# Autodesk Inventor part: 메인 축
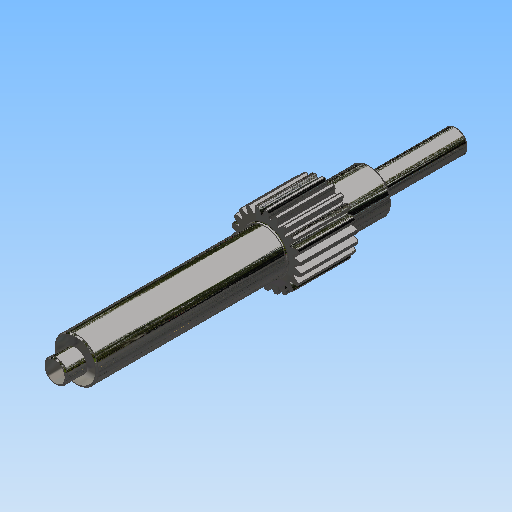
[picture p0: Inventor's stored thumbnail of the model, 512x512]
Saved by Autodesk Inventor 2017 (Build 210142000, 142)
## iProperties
Created: 2016-02
Part Number: 메인 축
Material: 강철, 연강
Document SubType Name: Modeling
Categories: <?xml version="1.0" encoding="UTF-16"?> <MemberInstance><Categories><FamilyTemplate><FamilyTemplateParameter ValueType="xs:double" Id="1" ObjectReferenceKey="da
Density: 7.86 g/cm^3
Mass: 187.503 g
Surface Area: 82.0529 cm^2
Volume: 23.8554 cm^3
Appearance: 강철 - 광택
Author: mdu
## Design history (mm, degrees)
sketch "Sketch1"
  geometry: C1 r 12 at (0, 0)
  constraints: 1 centre point
  dimensions: "d0" = 24 diameter of C1 (= da_da)
extrude "Extrusion1" new body sketch "Sketch1" distance "d1" = 20 (= da_b); taper "d2" = 0 deg
workplane "Work Plane2"
feature "피치 지름" dims "d4" = 10, "d5" = 0
workplane "Work Plane8"
workplane "Work Plane9"
chamfer "모따기1" distance "d49" = 0.2; stored, may be unused: second distance "d50" = 2, angle "d51" = 45 deg
sketch "스케치3"
  geometry: C1 r 7.5 at (0, 0); 1 further point
  constraints: 1 centre point, 1 coincident
  dimensions: "d52" = 15 diameter of C1
extrude "돌출2" join sketch "스케치3" distance "d53" = 66; taper "d54" = 0 deg
sketch "스케치4"
  geometry: C1 r 4 at (0, 0); 1 further point
  constraints: 1 centre point, 1 coincident
  dimensions: "d55" = 8 diameter of C1
extrude "돌출3" join sketch "스케치4" distance "d56" = 7; taper "d57" = 0 deg
sketch "스케치5"
  geometry: C1 r 7.5 at (0, 0) reference; C2 r 7.5 at (0, 0) reference; 1 further point
extrude "돌출4" join sketch "스케치5" distance "d62" = 16; taper "d63" = 0 deg
sketch "스케치6"
  geometry: C1 r 4 at (0, 0); 1 further point
  constraints: 1 centre point, 1 coincident
  dimensions: "d64" = 8 diameter of C1
extrude "돌출5" join sketch "스케치6" distance "d65" = 30; taper "d66" = 0 deg
chamfer "모따기2" distance "d58" = 0.5; stored, may be unused: second distance "d59" = 2, angle "d60" = 45 deg
fillet "모깎기1" dims "d61" = 0.5
feature "스퍼 기어" dims "da_b" = 20, "da_d" = 22, "da_aw" = 31, "da_da" = 24, "da_df" = 19.5, "da_dw" = 22, angle "da_beta" = 0 deg, "da_lefttooth" = 0, "da_righttooth" = 0
sketch "스케치7" dims "d68" = 18
  geometry: C1 r 0.25 at (0, -9); 2 further points
  constraints: 2 vertical alignment, 1 centre point, 1 coincident, 2 other
  dimensions: "d67" = 0.5 diameter of C1
extrude "돌출6" join sketch "스케치7" distance "d69" = 0.3; taper "d70" = 0 deg
body "Solid1"
sketch "Sketch2"
  geometry: C1 r 12 at (0, 0) reference; C2 r 11 at (0, 0)
  constraints: 1 centre point, 1 coincident
  dimensions: "d3" = 22 diameter of C2 (= da_dw)
body "Srf1"
node "투영된 루프1"
other parameters: "d16" = 31 (= da_aw), "d17" = 0, "d34" = 1.428 (computed from da_z), "d39" = 0, "d41" = 0, "d43" = 31 (= da_aw), "d46" = 31 (= da_aw), "d47" = 0, "d48" = 0
